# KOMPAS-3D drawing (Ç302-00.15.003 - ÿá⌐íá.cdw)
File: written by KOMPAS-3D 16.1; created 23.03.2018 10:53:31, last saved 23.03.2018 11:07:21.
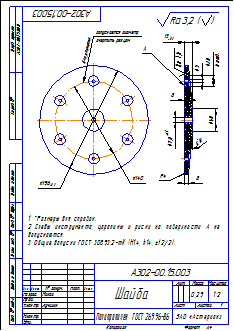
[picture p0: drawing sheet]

Sheet 1: A4, portrait

Title block, sheet 1: name: Шайба; designation: А302-00.15.003; material: Полипропилен  ГОСТ 26996-86; mass: 0,29; scale: 1:2; sheets: 1; organisation: ЗАО «Астерион»; sheet format: A4; stored path: \\192.168.87.28\Konstructor_doc\Мембранные насосы\Мембранный электропривод\А302-00.00.000 - ASTRA-302 (МЭ200)\Чертежи\А302-00.15.003 - Шайба.cdw; drawn by: Милов; technical control: Лучихин

Views: Вид 1, Местный разрез 1, Спереди, Проекционный вид 2
Referenced files in Z:\Мембранные насосы\Мембранный электропривод\А302-00.00.000 - ASTRA-302 (МЭ200)\3Д\: А302-00.15.003 - Шайба.m3d
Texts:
  Ra 1,6
  допускается диаметр
  очертить резцом
  для разметки
  *Размеры для справок.
  Следы инструмента, царапины и риски на поверхности  А  не
  допускаются.
  Общие допуски ГОСТ 30893.2-mK (H14, h14,  t2/2).
  Ra 3,2
  Ra 3,2 ( )
Dimensions and other numbers on the sheet: 15; 8; 20; 6 отв.; 5; 7,8; 40; 4; 140; 196; 1:2; 1; 0,29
